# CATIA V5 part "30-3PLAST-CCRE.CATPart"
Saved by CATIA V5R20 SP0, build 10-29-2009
Part number: 30-3PLAST-CCRE
Revision: ANY
Definition: UNKNOWN
Nomenclature: 30-3PLAST-CCRE
Source: Unknown
Bounding box of the stored display mesh (mm): x 0 to 50, y 0 to 23, z -30 to 0
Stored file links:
  C:\Users\Utente\Desktop\IO LAVORO\3D X SITO CF\CUMSA\3D files CC\CCHS5328\30-3PLAST-CCRE.CATPart
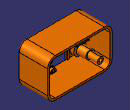
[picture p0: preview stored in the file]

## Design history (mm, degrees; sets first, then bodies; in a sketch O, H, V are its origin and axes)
Body1 "Cortar-Extruir28" (main body)
  Solid1: solid without history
